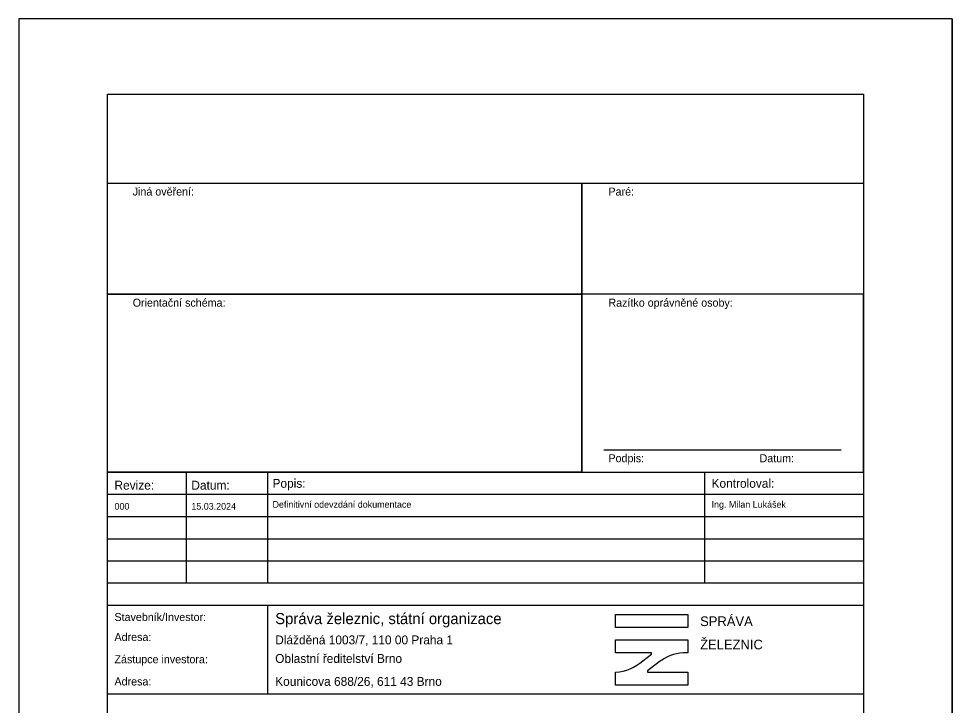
# Model space of a CAD drawing. Extents: x -172 to -151, y 333 to 362.7.
# Drawn here: x -172 to -151, y 347.25 to 362.7 of the extents above; entities that cross this region are included whole.
import ezdxf

# ---------------------------------------------------------------- set-up
doc = ezdxf.new("R2010")
doc.units = 0
for name, color, linetype in [('Default', 7, 'Continuous'), ('Rozpiska_Logo', 7, 'Continuous'), ('Rozpiska_pola_3', 7, 'Continuous'), ('Rozpiska_pole_1', 7, 'Continuous'), ('Rozpiska_pole_2', 7, 'Continuous'), ('Rozpiska_pole_4', 7, 'Continuous'), ('Rozpiska_pole_5', 7, 'Continuous'), ('Rozpiska_pole_6', 7, 'Continuous')]:
    doc.layers.add(name, color=color, linetype=linetype)

msp = doc.modelspace()

# ---------------------------------------------------------------- linework, layer by layer
at = {"layer": 'Default'}
for p, q in [((-151, 362.7), (-172, 362.7)), ((-172, 362.7), (-172, 333)), ((-151, 333), (-151, 362.7)), ((-151, 362.7), (-151, 333)), ((-159.335, 352.5), (-159.335, 359))]:
    msp.add_line(p, q, dxfattribs=at)
msp.add_lwpolyline([(-172, 333), (-151, 333), (-151, 362.7), (-172, 362.7)], close=True, dxfattribs=at)
at = {"layer": 'Rozpiska_Logo'}
for p, q in [((-157.96, 348.253), (-157.766, 348.399)), ((-157.766, 348.399), (-157.766, 348.434)), ((-157.597, 348.226), (-157.858, 348.024)), ((-157.858, 348.024), (-157.858, 347.993))]:
    msp.add_line(p, q, dxfattribs=at)
msp.add_lwpolyline([(-158.578, 349.291), (-156.948, 349.291), (-156.948, 348.998), (-158.578, 348.998)], close=True, dxfattribs=at)
for points in [[(-157.766, 348.434), (-158.578, 348.434), (-158.578, 348.727), (-156.948, 348.727), (-156.948, 348.434), (-157.056, 348.434)], [(-157.858, 347.993), (-156.948, 347.993), (-156.948, 347.7), (-158.578, 347.7), (-158.578, 347.993), (-158.572, 347.993)]]:
    msp.add_lwpolyline(points, dxfattribs=at)
for centre, radius, start, end in [((-156.982, 347.432), 1.004, 94.2142, 127.7808), ((-158.656, 349.042), 1.052, 274.6014, 311.4254)]:
    msp.add_arc(centre, radius, start, end, dxfattribs=at)
at = {"layer": 'Rozpiska_pola_3'}
msp.add_line((-158.835, 353), (-153.5, 353), dxfattribs=at)
at = {"layer": 'Rozpiska_pole_1'}
msp.add_lwpolyline([(-170, 361), (-153, 361), (-153, 334.5), (-170, 334.5)], close=True, dxfattribs=at)
at = {"layer": 'Rozpiska_pole_2'}
for points in [[(-170, 359), (-159.335, 359), (-159.335, 356.5), (-170, 356.5)], [(-159.335, 359), (-153, 359), (-153, 356.5), (-159.335, 356.5)], [(-170, 356.5), (-159.335, 356.5), (-159.335, 352.5), (-170, 352.5)], [(-153, 356.5), (-159.335, 356.5), (-159.335, 352.5), (-153, 352.5)]]:
    msp.add_lwpolyline(points, close=True, dxfattribs=at)
at = {"layer": 'Rozpiska_pole_4'}
for p, q in [((-168.223, 350), (-168.223, 352.5)), ((-166.395, 350), (-166.395, 352.5)), ((-156.57, 350), (-156.57, 352.5)), ((-170, 352), (-153, 352)), ((-170, 351.5), (-153, 351.5)), ((-170, 351), (-153, 351)), ((-170, 350.5), (-153, 350.5))]:
    msp.add_line(p, q, dxfattribs=at)
msp.add_lwpolyline([(-170, 352.5), (-153, 352.5), (-153, 350), (-170, 350)], close=True, dxfattribs=at)
at = {"layer": 'Rozpiska_pole_5'}
msp.add_line((-166.395, 347.5), (-166.395, 349.5), dxfattribs=at)
msp.add_lwpolyline([(-170, 349.5), (-153, 349.5), (-153, 347.5), (-170, 347.5)], close=True, dxfattribs=at)

# ---------------------------------------------------------------- texts
at = {"layer": 'Rozpiska_pola_3'}
for s, p in [('Paré:', (-158.735, 358.72)), ('Razítko oprávněné osoby:', (-158.735, 356.22)), ('Podpis:', (-158.735, 352.72)), ('Datum:', (-155.335, 352.72))]:
    msp.add_text(s, height=0.18, dxfattribs=at).set_placement(p)
at = {"layer": 'Rozpiska_pole_2'}
for s, p in [('Jiná ověření:', (-169.435, 358.72)), ('Orientační schéma:', (-169.435, 356.22))]:
    msp.add_text(s, height=0.18, dxfattribs=at).set_placement(p)
at = {"layer": 'Rozpiska_pole_4'}
for s, height, p in [('Revize:', 0.2, (-169.845, 352.103)), ('Datum:', 0.2, (-168.116, 352.103)), ('Popis:', 0.2, (-166.29, 352.145)), ('Kontroloval:', 0.2, (-156.415, 352.145)), ('000', 0.15, (-169.845, 351.653)), ('15.03.2024', 0.15, (-168.116, 351.653)), ('Definitivní odevzdání dokumentace', 0.15, (-166.29, 351.695)), ('Ing. Milan Lukášek', 0.15, (-156.415, 351.695))]:
    msp.add_text(s, height=height, dxfattribs=at).set_placement(p)
at = {"layer": 'Rozpiska_pole_5'}
for s, height, p in [('Stavebník/Investor:', 0.18, (-169.845, 349.147)), ('Správa železnic, státní organizace', 0.25, (-166.23, 349.077)), ('Adresa:', 0.18, (-169.845, 348.697)), ('Zástupce investora:', 0.18, (-169.845, 348.197)), ('Adresa:', 0.18, (-169.845, 347.697))]:
    msp.add_text(s, height=height, dxfattribs=at).set_placement(p)
at = {"layer": 'Rozpiska_pole_6'}
for s, height, p in [('SPRÁVA', 0.2183, (-156.673, 349.033)), ('Dlážděná 1003/7, 110 00 Praha 1', 0.2, (-166.23, 348.622)), ('ŽELEZNIC', 0.2183, (-156.673, 348.509)), ('Oblastní ředitelství Brno', 0.2, (-166.23, 348.204)), ('Kounicova 688/26, 611 43 Brno', 0.2, (-166.23, 347.688))]:
    msp.add_text(s, height=height, dxfattribs=at).set_placement(p)

doc.saveas('drawing.dxf')
